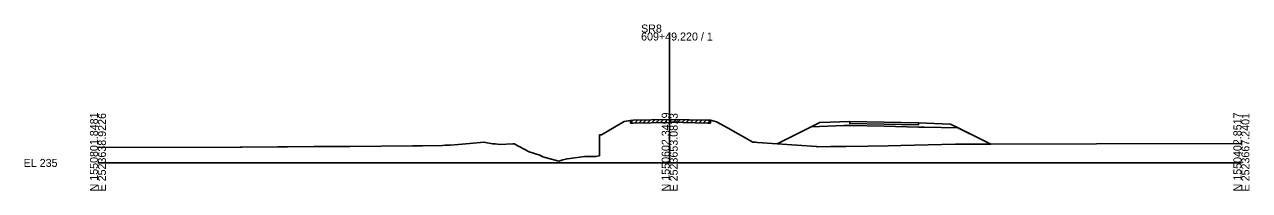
# Model space of a CAD drawing. Extents: x -26 to 2803, y -10 to 19537.
# Drawn here: x -25.7 to 402.8, y 15490.3 to 15548.6 of the extents above; entities that cross this region are included whole.
import ezdxf

# ---------------------------------------------------------------- set-up
doc = ezdxf.new("R2010")
doc.units = 0
for name, color, linetype in [('50', 7, 'Continuous'), ('XS_CELL', 7, 'Continuous'), ('XS_M_MULTI', 7, 'Continuous'), ('XS_M_SHAPES_EARTHWORK', 7, 'Continuous'), ('XS_P_FINISHED_GRADE', 7, 'Continuous'), ('XS_P_SUBGRADE_GRANULAR', 7, 'Continuous'), ('XS_P_SUBGRADE_PAVEMENT', 7, 'Continuous'), ('XS_X_GROUND', 7, 'Continuous')]:
    doc.layers.add(name, color=color, linetype=linetype)

msp = doc.modelspace()

# ---------------------------------------------------------------- linework, layer by layer
at = {"layer": '50'}
for p, q in [((186.27, 15513.92), (187.29, 15514.95)), ((186.27, 15513.92), (186.27, 15514.92)), ((186.27, 15513.92), (187.19, 15513.94)), ((187.19, 15513.94), (200, 15514.23)), ((187.77, 15513.96), (188.79, 15514.98)), ((189.27, 15513.99), (190.29, 15515.01)), ((190.77, 15514.02), (191.79, 15515.05)), ((192.27, 15514.06), (193.29, 15515.08)), ((193.77, 15514.09), (194.79, 15515.11)), ((195.27, 15514.12), (196.29, 15515.15)), ((196.77, 15514.16), (197.79, 15515.18)), ((198.27, 15514.19), (199.29, 15515.22)), ((199.77, 15514.23), (200.77, 15515.23)), ((200, 15514.23), (200.33, 15514.24)), ((200.33, 15514.24), (213.35, 15513.96)), ((201.27, 15514.22), (202.25, 15515.2)), ((202.77, 15514.19), (203.75, 15515.17)), ((204.27, 15514.15), (205.25, 15515.13)), ((205.77, 15514.12), (206.75, 15515.1)), ((207.27, 15514.09), (208.25, 15515.07)), ((208.77, 15514.06), (209.75, 15515.04)), ((210.27, 15514.03), (211.25, 15515.01)), ((211.77, 15513.99), (212.75, 15514.97)), ((213.27, 15513.96), (214.25, 15514.94)), ((213.35, 15513.96), (214.32, 15513.94)), ((214.32, 15514.94), (214.32, 15513.94))]:
    msp.add_line(p, q, dxfattribs=at)
at = {"layer": 'XS_CELL'}
for p, q in [((200, 15500), (200, 15545.72)), ((0, 15500), (200, 15500)), ((200, 15500), (400, 15500))]:
    msp.add_line(p, q, dxfattribs=at)
at = {"layer": 'XS_M_MULTI'}
for p, q in [((237.63, 15506.73), (252.53, 15514.15)), ((252.53, 15514.15), (263, 15514.57)), ((263, 15514.57), (275, 15514.33)), ((275, 15514.33), (287, 15514.09)), ((287, 15514.09), (298.2, 15513.64)), ((298.2, 15513.64), (312.3, 15506.61))]:
    msp.add_line(p, q, dxfattribs=at)
for points in [[(0, 15505.36), (49.77, 15505.49), (50.41, 15505.49), (62.91, 15505.59), (66.36, 15505.63), (75.47, 15505.7), (81.89, 15505.76), (88.06, 15505.81), (110.08, 15505.94), (113.49, 15505.99), (120.51, 15506.12), (121.57, 15506.19), (123.22, 15506.28), (126.16, 15506.46), (135.11, 15507.28), (135.61, 15507.18), (138.03, 15506.7), (138.91, 15506.7), (140.61, 15506.43), (145.19, 15506.68), (145.61, 15506.73), (150.8, 15503.88), (154.58, 15502.71), (155.63, 15502.16), (161.25, 15500.64), (162.66, 15501.04), (164.13, 15501.45), (165.24, 15501.54), (170.17, 15502.29), (173.85, 15502.24), (174.16, 15502.24), (175.4, 15502.5), (175.4, 15509.82), (175.75, 15509.82), (176.2, 15509.82), (181.3, 15512.84), (184.12, 15514.5), (186.27, 15514.92), (187.19, 15514.94), (200, 15515.23), (200.33, 15515.24), (213.35, 15514.96), (214.32, 15514.94), (216.41, 15514.43), (220.41, 15512.19), (229.11, 15507.32), (230.01, 15507.25), (230.75, 15507.2), (237.63, 15506.73)], [(312.3, 15506.61), (349.28, 15506.71), (400, 15506.8)]]:
    msp.add_lwpolyline(points, dxfattribs=at)
at = {"layer": 'XS_M_SHAPES_EARTHWORK'}
for points in [[(276.42, 15506.04), (280.91, 15506.14), (300.05, 15506.54), (311.15, 15506.61), (312.3, 15506.61), (300.87, 15512.31), (289, 15512.55), (287, 15512.59), (275, 15512.83), (263, 15513.07), (261, 15513.11), (249.52, 15512.65), (237.63, 15506.73), (251.33, 15505.78), (251.72, 15505.61), (256.41, 15505.75), (261.61, 15505.71), (269.43, 15505.88)], [(263, 15513.07), (261, 15513.11), (249.52, 15512.65), (252.53, 15514.15), (263, 15514.57), (263, 15513.82), (275, 15513.58), (287, 15513.34), (287, 15514.09), (298.2, 15513.64), (300.87, 15512.31), (289, 15512.55), (287, 15512.59), (275, 15512.83)], [(263, 15513.82), (263, 15514.57), (275, 15514.33), (287, 15514.09), (287, 15513.34), (275, 15513.58)]]:
    msp.add_lwpolyline(points, close=True, dxfattribs=at)
at = {"layer": 'XS_P_FINISHED_GRADE'}
for p, q in [((252.53, 15514.15), (237.63, 15506.73)), ((263, 15514.57), (252.53, 15514.15)), ((263, 15514.57), (275, 15514.33)), ((275, 15514.33), (287, 15514.09)), ((287, 15514.09), (298.2, 15513.64)), ((298.2, 15513.64), (312.3, 15506.61))]:
    msp.add_line(p, q, dxfattribs=at)
at = {"layer": 'XS_P_SUBGRADE_GRANULAR'}
for p, q in [((261, 15513.11), (249.52, 15512.65)), ((263, 15513.07), (261, 15513.11)), ((263, 15513.07), (275, 15512.83)), ((275, 15512.83), (287, 15512.59)), ((287, 15512.59), (289, 15512.55)), ((289, 15512.55), (300.87, 15512.31))]:
    msp.add_line(p, q, dxfattribs=at)
at = {"layer": 'XS_P_SUBGRADE_PAVEMENT'}
for p, q in [((263, 15513.82), (263, 15514.57)), ((263, 15513.82), (275, 15513.58)), ((275, 15513.58), (287, 15513.34)), ((287, 15513.34), (287, 15514.09))]:
    msp.add_line(p, q, dxfattribs=at)
at = {"layer": 'XS_X_GROUND'}
msp.add_lwpolyline([(0, 15505.36), (49.77, 15505.49), (50.41, 15505.49), (62.91, 15505.59), (66.36, 15505.63), (75.47, 15505.7), (81.89, 15505.76), (88.06, 15505.81), (110.08, 15505.94), (113.49, 15505.99), (120.51, 15506.12), (121.57, 15506.19), (123.22, 15506.28), (126.16, 15506.46), (135.11, 15507.28), (135.61, 15507.18), (138.03, 15506.7), (138.91, 15506.7), (140.61, 15506.43), (145.19, 15506.68), (145.61, 15506.73), (150.8, 15503.88), (154.58, 15502.71), (155.63, 15502.16), (161.25, 15500.64), (162.66, 15501.04), (164.13, 15501.45), (165.24, 15501.54), (170.17, 15502.29), (173.85, 15502.24), (174.16, 15502.24), (175.4, 15502.5), (175.4, 15509.82), (175.75, 15509.82), (176.2, 15509.82), (181.3, 15512.84), (184.12, 15514.5), (186.27, 15514.92), (187.19, 15514.94), (200, 15515.23), (200.33, 15515.24), (213.35, 15514.96), (214.32, 15514.94), (216.41, 15514.43), (220.41, 15512.19), (229.11, 15507.32), (230.01, 15507.25), (230.75, 15507.2), (251.33, 15505.78), (251.72, 15505.61), (256.41, 15505.75), (261.61, 15505.71), (269.43, 15505.88), (276.42, 15506.04), (280.91, 15506.14), (300.05, 15506.54), (311.15, 15506.61), (349.28, 15506.71), (400, 15506.8)], dxfattribs=at)

# ---------------------------------------------------------------- texts
at = {"layer": 'XS_CELL'}
for s, p in [('SR8', (190, 15545.72)), ('609+49.220 / 1', (190, 15542.92)), ('EL 235', (-26, 15498.6))]:
    msp.add_text(s, height=2.8, dxfattribs=at).set_placement(p)
for s, p in [('N 1550801.8481', (0, 15490)), ('E 2523638.9226', (2.8, 15490)), ('N 1550602.3499', (200, 15490)), ('E 2523653.0813', (202.8, 15490)), ('N 1550402.8517', (400, 15490)), ('E 2523667.2401', (402.8, 15490))]:
    msp.add_text(s, height=2.8, rotation=90, dxfattribs=at).set_placement(p)

doc.saveas('drawing.dxf')
